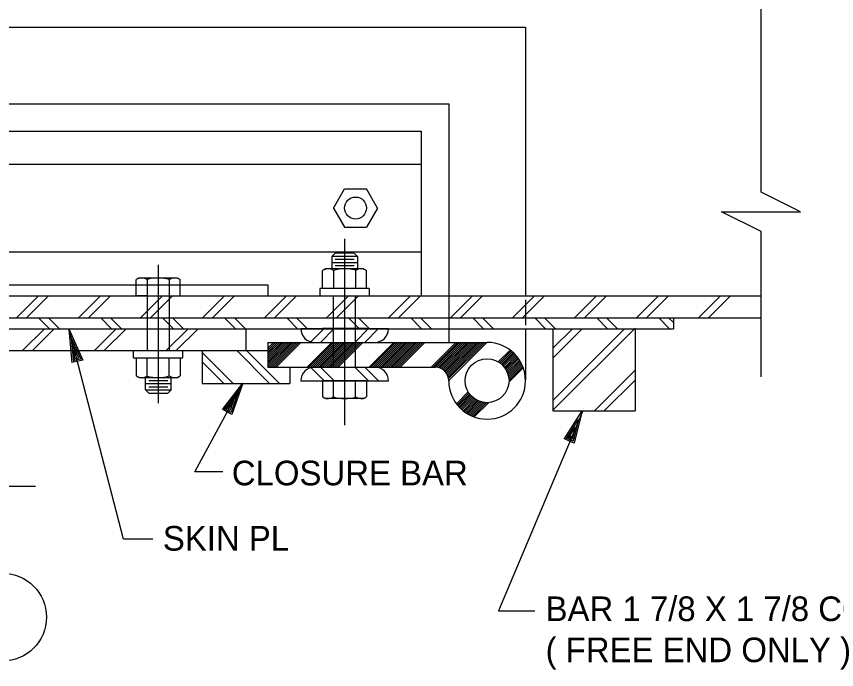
# Model space of a CAD drawing. Extents: x 22371.58 to 22374.41, y 22370.57 to 22372.4.
# Drawn here: x 22372.3521 to 22372.7418, y 22370.9898 to 22371.3 of the extents above; entities that cross this region are included whole.
import ezdxf

# ---------------------------------------------------------------- set-up
doc = ezdxf.new("R2010")
doc.units = 0
for name, color, linetype in [('S-ANNO-DIMS', 7, 'Continuous'), ('S-ANNO-TEXT', 7, 'Continuous'), ('S-GATE-SEAL', 7, 'Continuous'), ('S-SECT-MISC', 7, 'Continuous'), ('S-SECT-SHPS', 7, 'Continuous')]:
    doc.layers.add(name, color=color, linetype=linetype)

msp = doc.modelspace()

# ---------------------------------------------------------------- linework, layer by layer
at = {"layer": 'S-ANNO-DIMS'}
for p, q in [((22372.70594815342, 22371.216615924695), (22372.70594815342, 22371.370740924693)), ((22372.70594815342, 22371.128928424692), (22372.70594815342, 22371.197928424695)), ((22372.37718773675, 22371.151303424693), (22372.37718773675, 22371.151303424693)), ((22372.378271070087, 22371.14710550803), (22372.378271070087, 22371.14710550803)), ((22372.45963565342, 22371.12584509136), (22372.45963565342, 22371.12584509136)), ((22372.45757315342, 22371.12203259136), (22372.45757315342, 22371.12203259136)), ((22372.621312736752, 22371.112678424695), (22372.581165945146, 22371.017772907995)), ((22372.581165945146, 22371.017772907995), (22372.59840552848, 22371.017772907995))]:
    msp.add_line(p, q, dxfattribs=at)
for points in [[(22372.70594815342, 22371.197928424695), (22372.68719815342, 22371.207240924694), (22372.724656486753, 22371.207240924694), (22372.70594815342, 22371.216615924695)], [(22372.41688565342, 22371.051824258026), (22372.402968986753, 22371.051824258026), (22372.37718773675, 22371.151303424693)], [(22372.378593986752, 22371.135574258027), (22372.37718773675, 22371.151303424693), (22372.383593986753, 22371.136865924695), (22372.37932315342, 22371.13576175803), (22372.378271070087, 22371.14710550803), (22372.38262523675, 22371.137303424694), (22372.37988565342, 22371.13659509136), (22372.37932315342, 22371.143074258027), (22372.381646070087, 22371.137740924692), (22372.380521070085, 22371.13744925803), (22372.38040648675, 22371.13887634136)], [(22372.45013565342, 22371.083740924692), (22372.436906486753, 22371.083740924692), (22372.45963565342, 22371.12584509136)], [(22372.449958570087, 22371.113355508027), (22372.45963565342, 22371.12584509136), (22372.45451065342, 22371.11090759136), (22372.450614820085, 22371.11300134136), (22372.45757315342, 22371.12203259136), (22372.45409398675, 22371.111886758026), (22372.451593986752, 22371.11323050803), (22372.455593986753, 22371.118365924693), (22372.453677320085, 22371.112865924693), (22372.452646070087, 22371.113428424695), (22372.45354190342, 22371.114553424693)], [(22372.61241690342, 22371.099334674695), (22372.620864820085, 22371.112678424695), (22372.617177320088, 22371.09731384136), (22372.61310440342, 22371.099043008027), (22372.619177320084, 22371.10868884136), (22372.61666690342, 22371.098251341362), (22372.614052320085, 22371.099355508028), (22372.617552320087, 22371.104845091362), (22372.616156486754, 22371.099199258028), (22372.615083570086, 22371.099647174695), (22372.615864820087, 22371.100855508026)]]:
    msp.add_lwpolyline(points, dxfattribs=at)
at = {"layer": 'S-ANNO-TEXT'}
msp.add_line((22372.153187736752, 22371.076886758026), (22372.36113565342, 22371.076886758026), dxfattribs=at)
msp.add_circle((22372.34553409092, 22371.014738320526), 0.020833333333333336, dxfattribs=at)
at = {"layer": 'S-GATE-SEAL'}
for p, q in [((22371.810114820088, 22371.29497009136), (22372.593968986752, 22371.29497009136)), ((22372.593968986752, 22371.29497009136), (22372.593968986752, 22371.167365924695)), ((22371.810114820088, 22371.258511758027), (22372.55751065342, 22371.258511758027)), ((22372.55751065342, 22371.258511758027), (22372.55751065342, 22371.145230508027)), ((22371.810114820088, 22371.245490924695), (22372.544489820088, 22371.245490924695)), ((22372.544489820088, 22371.245490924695), (22372.544489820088, 22371.167365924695)), ((22371.810114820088, 22371.229865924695), (22372.544489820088, 22371.229865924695)), ((22371.810114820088, 22371.188199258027), (22372.544489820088, 22371.188199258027)), ((22371.810114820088, 22371.172574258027), (22372.47157315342, 22371.172574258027)), ((22372.47157315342, 22371.172574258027), (22372.47157315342, 22371.167365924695)), ((22371.810114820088, 22371.167365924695), (22372.70594815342, 22371.167365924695)), ((22372.593968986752, 22371.165459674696), (22372.593968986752, 22371.153386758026)), ((22371.810114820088, 22371.156949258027), (22372.70594815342, 22371.156949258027)), ((22372.664281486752, 22371.156949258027), (22372.664281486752, 22371.151740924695)), ((22371.810114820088, 22371.151740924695), (22372.664281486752, 22371.151740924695)), ((22372.461156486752, 22371.151740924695), (22372.461156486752, 22371.141324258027)), ((22372.48719815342, 22371.15175134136), (22372.528864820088, 22371.15175134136)), ((22372.593968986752, 22371.151740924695), (22372.593968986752, 22371.127428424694)), ((22372.606989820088, 22371.151740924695), (22372.606989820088, 22371.112678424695)), ((22372.646052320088, 22371.151740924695), (22372.646052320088, 22371.112678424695)), ((22372.47157315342, 22371.145230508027), (22372.47157315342, 22371.133511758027)), ((22372.47157315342, 22371.145230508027), (22372.575739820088, 22371.145230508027)), ((22372.493708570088, 22371.145240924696), (22372.52235440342, 22371.145240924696)), ((22371.810114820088, 22371.141324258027), (22372.47157315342, 22371.141324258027)), ((22372.44032315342, 22371.141324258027), (22372.44032315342, 22371.125699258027)), ((22372.47157315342, 22371.133511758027), (22372.551000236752, 22371.133511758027)), ((22372.481989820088, 22371.133511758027), (22372.481989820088, 22371.125699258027)), ((22372.493708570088, 22371.133511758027), (22372.52235440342, 22371.133511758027)), ((22372.44032315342, 22371.125699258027), (22372.481989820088, 22371.125699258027)), ((22372.48719815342, 22371.12700134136), (22372.528864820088, 22371.12700134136)), ((22372.606989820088, 22371.112678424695), (22372.646052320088, 22371.112678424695))]:
    msp.add_line(p, q, dxfattribs=at)
msp.add_circle((22372.575750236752, 22371.12699613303), 0.010416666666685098, dxfattribs=at)
for centre, radius, start, end in [((22372.493708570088, 22371.151753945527), 0.006510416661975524, 180, 269.9999972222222), ((22372.52235440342, 22371.151753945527), 0.006510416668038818, 270.0000027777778, 0), ((22372.575750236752, 22371.12699613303), 0.01822916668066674, 179.99999999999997, 89.99999722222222), ((22372.493708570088, 22371.126998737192), 0.006510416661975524, 90.00000277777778, 180), ((22372.52235440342, 22371.126998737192), 0.006510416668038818, 0, 89.99999722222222), ((22372.55101065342, 22371.12699613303), 0.006510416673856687, 0, 89.99999722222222)]:
    msp.add_arc(centre, radius, start, end, dxfattribs=at)
at = {"layer": 'S-SECT-MISC'}
for p, q in [((22372.502771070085, 22371.20903259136), (22372.508021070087, 22371.218126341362)), ((22372.508021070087, 22371.218126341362), (22372.518468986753, 22371.218126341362)), ((22372.52371898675, 22371.20903259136), (22372.518468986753, 22371.218126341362)), ((22372.502771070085, 22371.20903259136), (22372.508021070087, 22371.19993884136)), ((22372.52371898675, 22371.20903259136), (22372.518468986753, 22371.19993884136)), ((22372.508021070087, 22371.19993884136), (22372.518468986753, 22371.19993884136)), ((22372.508031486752, 22371.194365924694), (22372.508031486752, 22371.105845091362)), ((22372.50196898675, 22371.18606384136), (22372.503479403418, 22371.187574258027)), ((22372.50196898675, 22371.18606384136), (22372.50196898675, 22371.180199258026)), ((22372.514093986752, 22371.18606384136), (22372.50196898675, 22371.18606384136)), ((22372.51257315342, 22371.187574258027), (22372.503479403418, 22371.187574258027)), ((22372.512562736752, 22371.18454300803), (22372.503541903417, 22371.18454300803)), ((22372.514093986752, 22371.18606384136), (22372.51257315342, 22371.187574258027)), ((22372.514093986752, 22371.18606384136), (22372.514093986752, 22371.180199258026)), ((22372.419489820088, 22371.182074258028), (22372.419489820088, 22371.11631384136)), ((22372.498968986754, 22371.180199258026), (22372.497562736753, 22371.179386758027)), ((22372.517093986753, 22371.180199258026), (22372.498968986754, 22371.180199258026)), ((22372.514093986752, 22371.18303259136), (22372.50196898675, 22371.18303259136)), ((22372.512562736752, 22371.181522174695), (22372.503541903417, 22371.181522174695)), ((22372.517093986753, 22371.180199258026), (22372.518500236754, 22371.179386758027)), ((22372.497562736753, 22371.17075134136), (22372.497562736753, 22371.179386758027)), ((22372.50279190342, 22371.17940759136), (22372.50279190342, 22371.17075134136)), ((22372.513271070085, 22371.17940759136), (22372.513271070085, 22371.17075134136)), ((22372.518500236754, 22371.17075134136), (22372.518500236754, 22371.179386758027)), ((22372.410427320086, 22371.175845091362), (22372.409021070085, 22371.17503259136)), ((22372.409021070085, 22371.167365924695), (22372.409021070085, 22371.17503259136)), ((22372.410427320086, 22371.175845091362), (22372.428552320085, 22371.175845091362)), ((22372.414250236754, 22371.175053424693), (22372.414250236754, 22371.167365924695)), ((22372.424739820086, 22371.175053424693), (22372.424739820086, 22371.167365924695)), ((22372.428552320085, 22371.175845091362), (22372.429958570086, 22371.17503259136)), ((22372.429958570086, 22371.167365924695), (22372.429958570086, 22371.17503259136)), ((22372.496312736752, 22371.17075134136), (22372.496312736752, 22371.167365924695)), ((22372.519750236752, 22371.17075134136), (22372.496312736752, 22371.17075134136)), ((22372.519750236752, 22371.17075134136), (22372.519750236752, 22371.167365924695)), ((22372.409021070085, 22371.167365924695), (22372.429958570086, 22371.167365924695)), ((22372.414323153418, 22371.167365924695), (22372.409021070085, 22371.167365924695)), ((22372.414281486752, 22371.167365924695), (22372.414281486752, 22371.141324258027)), ((22372.42469815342, 22371.167365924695), (22372.42469815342, 22371.141324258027)), ((22372.50282315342, 22371.133511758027), (22372.50282315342, 22371.167365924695)), ((22372.513239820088, 22371.133511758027), (22372.513239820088, 22371.167365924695)), ((22372.42331273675, 22371.141324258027), (22372.43372940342, 22371.151740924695)), ((22372.428031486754, 22371.141324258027), (22372.438448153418, 22371.151740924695)), ((22372.518500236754, 22371.15175134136), (22372.497562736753, 22371.15175134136)), ((22372.513198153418, 22371.15175134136), (22372.518500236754, 22371.15175134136)), ((22372.407771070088, 22371.137928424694), (22372.407771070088, 22371.141324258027)), ((22372.431208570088, 22371.137928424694), (22372.431208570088, 22371.141324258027)), ((22372.407771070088, 22371.137928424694), (22372.431208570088, 22371.137928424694)), ((22372.409031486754, 22371.137928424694), (22372.409031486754, 22371.129293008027)), ((22372.414250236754, 22371.129272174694), (22372.414250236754, 22371.137928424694)), ((22372.424739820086, 22371.129272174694), (22372.424739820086, 22371.137928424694)), ((22372.429958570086, 22371.137928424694), (22372.429958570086, 22371.129293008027)), ((22372.410427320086, 22371.12848050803), (22372.409031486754, 22371.129293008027)), ((22372.410427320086, 22371.12848050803), (22372.428562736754, 22371.12848050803)), ((22372.41343773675, 22371.12262634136), (22372.41343773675, 22371.12848050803)), ((22372.41343773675, 22371.12565759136), (22372.425562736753, 22371.12565759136)), ((22372.41496898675, 22371.127168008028), (22372.42397940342, 22371.127168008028)), ((22372.425562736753, 22371.12262634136), (22372.425562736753, 22371.12848050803)), ((22372.428562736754, 22371.12848050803), (22372.429958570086, 22371.129293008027)), ((22372.518500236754, 22371.12700134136), (22372.497562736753, 22371.12700134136)), ((22372.497562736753, 22371.12700134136), (22372.497562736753, 22371.119324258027)), ((22372.502781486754, 22371.119303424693), (22372.502781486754, 22371.12700134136)), ((22372.513271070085, 22371.119303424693), (22372.513271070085, 22371.12700134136)), ((22372.518500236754, 22371.12700134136), (22372.518500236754, 22371.119324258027)), ((22372.41343773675, 22371.12262634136), (22372.425562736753, 22371.12262634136)), ((22372.41343773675, 22371.12262634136), (22372.41494815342, 22371.121105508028)), ((22372.41496898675, 22371.124136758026), (22372.42397940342, 22371.124136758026)), ((22372.425562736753, 22371.12262634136), (22372.424041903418, 22371.121105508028)), ((22372.41494815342, 22371.121105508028), (22372.424041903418, 22371.121105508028)), ((22372.498968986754, 22371.118511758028), (22372.497562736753, 22371.119324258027)), ((22372.517093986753, 22371.118511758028), (22372.498968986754, 22371.118511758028)), ((22372.517093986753, 22371.118511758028), (22372.518500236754, 22371.119324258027))]:
    msp.add_line(p, q, dxfattribs=at)
for points in [[(22372.411083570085, 22371.156949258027), (22372.421500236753, 22371.167365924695)], [(22372.41579190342, 22371.156949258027), (22372.42621898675, 22371.167365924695)], [(22372.499468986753, 22371.15693884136), (22372.50988565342, 22371.167365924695)], [(22372.50418773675, 22371.156949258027), (22372.51460440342, 22371.167365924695)], [(22372.42679190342, 22371.151740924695), (22372.421583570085, 22371.156949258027)], [(22372.43151065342, 22371.151730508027), (22372.426302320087, 22371.156949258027)], [(22372.515187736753, 22371.151730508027), (22372.509968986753, 22371.156949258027)], [(22372.519896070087, 22371.151730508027), (22372.51468773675, 22371.156949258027)], [(22372.498333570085, 22371.15175134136), (22372.49204190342, 22371.145459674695)], [(22372.50304190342, 22371.15175134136), (22372.49654190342, 22371.145240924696)], [(22372.519468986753, 22371.15175134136), (22372.512958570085, 22371.145240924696)]]:
    msp.add_lwpolyline(points, dxfattribs=at)
msp.add_circle((22372.513245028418, 22371.209029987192), 0.005208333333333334, dxfattribs=at)
for centre, radius, start, end in [((22372.500211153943, 22371.175664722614), 0.004545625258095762, 55.489019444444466, 120.28758611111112), ((22372.508097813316, 22371.16202027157), 0.018182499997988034, 73.50340833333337, 106.98162777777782), ((22372.515848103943, 22371.175664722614), 0.004545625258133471, 59.71241111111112, 124.5109777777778), ((22372.41167664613, 22371.171309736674), 0.004545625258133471, 55.489019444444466, 120.28758611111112), ((22372.419426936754, 22371.157665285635), 0.018182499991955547, 73.01836944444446, 106.49658888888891), ((22372.427313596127, 22371.171309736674), 0.004545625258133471, 59.71241111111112, 124.5109777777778), ((22372.411678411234, 22371.13302025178), 0.004545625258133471, 239.71241111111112, 304.5109777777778), ((22372.419428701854, 22371.14666470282), 0.018182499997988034, 253.50340833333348, 286.98162777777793), ((22372.427315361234, 22371.13302025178), 0.004545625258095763, 235.48901944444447, 300.2875861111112), ((22372.500212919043, 22371.12305232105), 0.004545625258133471, 239.71241111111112, 304.5109777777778), ((22372.50809957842, 22371.136696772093), 0.018182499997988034, 253.01837222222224, 286.4965916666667), ((22372.515849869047, 22371.12305232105), 0.004545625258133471, 235.48901944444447, 300.2875861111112)]:
    msp.add_arc(centre, radius, start, end, dxfattribs=at)
at = {"layer": 'S-SECT-SHPS'}
for p, q in [((22372.354958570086, 22371.141324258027), (22372.365375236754, 22371.151740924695)), ((22372.358771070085, 22371.151740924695), (22372.358771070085, 22371.151740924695)), ((22372.359677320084, 22371.141324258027), (22372.370093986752, 22371.151740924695)), ((22372.38913565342, 22371.141324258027), (22372.399552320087, 22371.151740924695)), ((22372.39385440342, 22371.141324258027), (22372.404271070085, 22371.151740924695)), ((22372.36126065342, 22371.148188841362), (22372.36126065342, 22371.148188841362)), ((22372.48166690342, 22371.145230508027), (22372.47157315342, 22371.13513675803)), ((22372.47982315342, 22371.145230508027), (22372.47157315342, 22371.13698050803)), ((22372.47797940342, 22371.145230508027), (22372.47157315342, 22371.13882425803)), ((22372.476146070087, 22371.145230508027), (22372.47157315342, 22371.14065759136)), ((22372.474302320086, 22371.145230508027), (22372.47157315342, 22371.14250134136)), ((22372.475218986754, 22371.145230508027), (22372.47157315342, 22371.141584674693)), ((22372.477062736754, 22371.145230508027), (22372.47157315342, 22371.139740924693)), ((22372.47890648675, 22371.145230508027), (22372.47157315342, 22371.137897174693)), ((22372.48075023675, 22371.145230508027), (22372.47157315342, 22371.136053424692)), ((22372.482583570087, 22371.145230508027), (22372.47157315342, 22371.13422009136)), ((22372.48351065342, 22371.145230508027), (22372.47179190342, 22371.133511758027)), ((22372.484427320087, 22371.145230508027), (22372.472708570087, 22371.133511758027)), ((22372.48534398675, 22371.145230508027), (22372.47362523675, 22371.133511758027)), ((22372.486271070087, 22371.145230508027), (22372.474552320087, 22371.133511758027)), ((22372.48718773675, 22371.145230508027), (22372.47546898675, 22371.133511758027)), ((22372.50191690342, 22371.145230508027), (22372.49019815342, 22371.133511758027)), ((22372.502833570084, 22371.145230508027), (22372.491114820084, 22371.133511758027)), ((22372.50376065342, 22371.145230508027), (22372.49204190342, 22371.133511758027)), ((22372.504677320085, 22371.145230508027), (22372.492958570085, 22371.133511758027)), ((22372.50560440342, 22371.145230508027), (22372.49388565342, 22371.133511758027)), ((22372.506521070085, 22371.145230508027), (22372.494802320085, 22371.133511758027)), ((22372.507437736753, 22371.145230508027), (22372.495718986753, 22371.133511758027)), ((22372.508364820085, 22371.145230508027), (22372.496646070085, 22371.133511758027)), ((22372.509281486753, 22371.145230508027), (22372.497562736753, 22371.133511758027)), ((22372.51019815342, 22371.145230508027), (22372.49847940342, 22371.133511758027)), ((22372.511125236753, 22371.145230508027), (22372.499406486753, 22371.133511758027)), ((22372.512041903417, 22371.145230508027), (22372.500323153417, 22371.133511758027)), ((22372.512968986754, 22371.145230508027), (22372.501250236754, 22371.133511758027)), ((22372.513885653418, 22371.145230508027), (22372.502166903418, 22371.133511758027)), ((22372.514802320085, 22371.145230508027), (22372.503083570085, 22371.133511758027)), ((22372.515729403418, 22371.145230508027), (22372.504010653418, 22371.133511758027)), ((22372.516646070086, 22371.145230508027), (22372.504927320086, 22371.133511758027)), ((22372.53138565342, 22371.145230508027), (22372.51966690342, 22371.133511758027)), ((22372.532302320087, 22371.145230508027), (22372.520583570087, 22371.133511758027)), ((22372.53321898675, 22371.145230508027), (22372.52150023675, 22371.133511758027)), ((22372.534146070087, 22371.145230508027), (22372.522427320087, 22371.133511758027)), ((22372.53506273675, 22371.145230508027), (22372.52334398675, 22371.133511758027)), ((22372.53597940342, 22371.145230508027), (22372.52426065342, 22371.133511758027)), ((22372.536906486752, 22371.145230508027), (22372.525187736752, 22371.133511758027)), ((22372.53782315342, 22371.145230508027), (22372.52610440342, 22371.133511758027)), ((22372.538750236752, 22371.145230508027), (22372.527031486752, 22371.133511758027)), ((22372.53966690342, 22371.145230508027), (22372.52794815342, 22371.133511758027)), ((22372.540583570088, 22371.145230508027), (22372.528864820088, 22371.133511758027)), ((22372.54151065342, 22371.145230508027), (22372.52979190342, 22371.133511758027)), ((22372.542427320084, 22371.145230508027), (22372.530708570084, 22371.133511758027)), ((22372.543343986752, 22371.145230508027), (22372.531625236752, 22371.133511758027)), ((22372.544271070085, 22371.145230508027), (22372.532552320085, 22371.133511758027)), ((22372.545187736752, 22371.145230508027), (22372.533468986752, 22371.133511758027)), ((22372.546114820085, 22371.145230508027), (22372.534396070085, 22371.133511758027)), ((22372.560843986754, 22371.145230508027), (22372.549125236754, 22371.133511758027)), ((22372.561771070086, 22371.145230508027), (22372.550052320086, 22371.133511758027)), ((22372.562677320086, 22371.14522009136), (22372.550958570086, 22371.13350134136)), ((22372.563604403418, 22371.145230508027), (22372.551833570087, 22371.133449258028)), ((22372.564521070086, 22371.14522009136), (22372.55260440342, 22371.133303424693)), ((22372.56544815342, 22371.145230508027), (22372.553312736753, 22371.133084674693)), ((22372.566364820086, 22371.14522009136), (22372.553948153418, 22371.132803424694)), ((22372.56729190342, 22371.145230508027), (22372.554531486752, 22371.13247009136)), ((22372.568208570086, 22371.14522009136), (22372.55507315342, 22371.132084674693)), ((22372.56913565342, 22371.145230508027), (22372.555531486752, 22371.13162634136)), ((22372.57004190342, 22371.14522009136), (22372.556000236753, 22371.131178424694)), ((22372.57096898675, 22371.145230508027), (22372.556458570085, 22371.13072009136)), ((22372.57188565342, 22371.14522009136), (22372.556739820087, 22371.130074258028)), ((22372.57281273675, 22371.145230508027), (22372.55704190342, 22371.129449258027)), ((22372.57372940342, 22371.14522009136), (22372.557271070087, 22371.128772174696)), ((22372.57465648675, 22371.145230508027), (22372.557437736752, 22371.128011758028)), ((22372.57557315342, 22371.14522009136), (22372.557521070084, 22371.127168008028)), ((22372.47241690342, 22371.125699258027), (22372.45679190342, 22371.141324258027)), ((22372.47707315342, 22371.125699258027), (22372.46144815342, 22371.141324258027)), ((22372.58666690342, 22371.14159509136), (22372.58104190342, 22371.13597009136)), ((22372.587187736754, 22371.14118884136), (22372.581604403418, 22371.13560550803)), ((22372.455021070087, 22371.125699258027), (22372.44032315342, 22371.140397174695)), ((22372.587687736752, 22371.140772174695), (22372.582135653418, 22371.13522009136)), ((22372.588146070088, 22371.140313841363), (22372.582646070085, 22371.134803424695)), ((22372.588646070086, 22371.13988675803), (22372.583114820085, 22371.134355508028)), ((22372.589104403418, 22371.139418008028), (22372.58357315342, 22371.133897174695)), ((22372.589531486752, 22371.138928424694), (22372.58397940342, 22371.13337634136)), ((22372.589948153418, 22371.138428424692), (22372.584437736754, 22371.13291800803)), ((22372.59035440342, 22371.13790759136), (22372.584718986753, 22371.13228259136)), ((22372.590739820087, 22371.13737634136), (22372.585052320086, 22371.13168884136)), ((22372.450614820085, 22371.125699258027), (22372.44032315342, 22371.135990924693)), ((22372.59110440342, 22371.13682425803), (22372.585343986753, 22371.13106384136)), ((22372.59144815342, 22371.136251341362), (22372.585593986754, 22371.130397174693)), ((22372.591781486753, 22371.13565759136), (22372.585812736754, 22371.12968884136)), ((22372.59210440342, 22371.135053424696), (22372.58597940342, 22371.12893884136)), ((22372.592396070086, 22371.134428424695), (22372.58610440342, 22371.128136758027)), ((22372.59266690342, 22371.13378259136), (22372.58616690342, 22371.127282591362)), ((22372.59291690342, 22371.133115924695), (22372.586146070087, 22371.126334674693)), ((22372.513198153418, 22371.12700134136), (22372.518500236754, 22371.12700134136)), ((22372.566781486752, 22371.121699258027), (22372.561156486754, 22371.11607425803)), ((22372.56713565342, 22371.12113675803), (22372.561614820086, 22371.115615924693)), ((22372.567521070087, 22371.120605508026), (22372.561968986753, 22371.115053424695)), ((22372.567937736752, 22371.120105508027), (22372.562437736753, 22371.11459509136)), ((22372.56838565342, 22371.119626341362), (22372.562864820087, 22371.114105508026)), ((22372.56884398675, 22371.119168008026), (22372.56332315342, 22371.113636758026)), ((22372.569364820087, 22371.11876175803), (22372.563812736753, 22371.11322009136)), ((22372.569896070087, 22371.11837634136), (22372.56431273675, 22371.112793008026)), ((22372.570458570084, 22371.118022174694), (22372.564833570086, 22371.112397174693)), ((22372.57106273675, 22371.117699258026), (22372.565375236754, 22371.11201175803)), ((22372.571687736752, 22371.117407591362), (22372.56591690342, 22371.11163675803)), ((22372.57235440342, 22371.117147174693), (22372.566489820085, 22371.111293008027)), ((22372.573052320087, 22371.116928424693), (22372.567083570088, 22371.110959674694)), ((22372.573802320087, 22371.11676175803), (22372.56768773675, 22371.110647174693)), ((22372.57460440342, 22371.116636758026), (22372.568312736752, 22371.110355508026)), ((22372.575468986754, 22371.116584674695), (22372.568958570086, 22371.110074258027)), ((22372.57640648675, 22371.11659509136), (22372.569625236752, 22371.109824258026)), ((22372.621416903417, 22371.113980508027), (22372.621416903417, 22371.113980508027)), ((22372.61972940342, 22371.109990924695), (22372.61972940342, 22371.109990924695))]:
    msp.add_line(p, q, dxfattribs=at)
for points in [[(22372.35215648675, 22371.156949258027), (22372.36257315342, 22371.167365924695)], [(22372.356875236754, 22371.156949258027), (22372.367291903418, 22371.167365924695)], [(22372.381614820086, 22371.156949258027), (22372.39204190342, 22371.167365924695)], [(22372.386333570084, 22371.156949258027), (22372.396750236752, 22371.167365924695)], [(22372.44054190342, 22371.156949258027), (22372.450958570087, 22371.167365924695)], [(22372.445260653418, 22371.156949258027), (22372.455677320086, 22371.167365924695)], [(22372.47001065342, 22371.156949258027), (22372.480427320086, 22371.167365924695)], [(22372.474718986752, 22371.156949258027), (22372.48513565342, 22371.167365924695)], [(22372.52893773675, 22371.156949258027), (22372.53935440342, 22371.167365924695)], [(22372.533646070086, 22371.156949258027), (22372.544062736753, 22371.167365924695)], [(22372.558396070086, 22371.156949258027), (22372.568812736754, 22371.167365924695)], [(22372.563114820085, 22371.156949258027), (22372.573531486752, 22371.167365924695)], [(22372.58785440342, 22371.156949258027), (22372.598271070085, 22371.167365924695)], [(22372.59257315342, 22371.156949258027), (22372.602989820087, 22371.167365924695)], [(22372.61732315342, 22371.156949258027), (22372.627739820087, 22371.167365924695)], [(22372.622031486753, 22371.156949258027), (22372.632448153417, 22371.167365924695)], [(22372.646781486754, 22371.15693884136), (22372.657198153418, 22371.167365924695)], [(22372.651500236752, 22371.15693884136), (22372.66191690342, 22371.167365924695)], [(22372.676250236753, 22371.156949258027), (22372.68666690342, 22371.167365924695)], [(22372.680958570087, 22371.156949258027), (22372.69137523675, 22371.167365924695)], [(22372.367875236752, 22371.151730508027), (22372.36265648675, 22371.156949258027)], [(22372.372583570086, 22371.151740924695), (22372.367375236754, 22371.156949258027)], [(22372.397333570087, 22371.151730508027), (22372.39212523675, 22371.156949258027)], [(22372.402052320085, 22371.151730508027), (22372.396833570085, 22371.156949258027)], [(22372.45626065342, 22371.151740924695), (22372.45104190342, 22371.156949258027)], [(22372.460968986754, 22371.151740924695), (22372.455760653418, 22371.156949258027)], [(22372.48571898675, 22371.151730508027), (22372.48051065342, 22371.156949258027)], [(22372.490437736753, 22371.151740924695), (22372.48522940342, 22371.156949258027)], [(22372.544646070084, 22371.151740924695), (22372.539437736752, 22371.156949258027)], [(22372.549364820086, 22371.151730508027), (22372.544146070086, 22371.156949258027)], [(22372.57410440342, 22371.151740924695), (22372.568896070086, 22371.156949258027)], [(22372.57882315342, 22371.151740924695), (22372.573614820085, 22371.156949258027)], [(22372.603573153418, 22371.151730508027), (22372.598364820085, 22371.156949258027)], [(22372.60828148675, 22371.151740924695), (22372.60307315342, 22371.156949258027)], [(22372.633031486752, 22371.151730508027), (22372.62782315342, 22371.156949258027)], [(22372.637750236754, 22371.151730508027), (22372.63254190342, 22371.156949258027)], [(22372.66250023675, 22371.151740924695), (22372.65729190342, 22371.156949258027)], [(22372.664281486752, 22371.15466800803), (22372.662000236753, 22371.156949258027)], [(22372.705708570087, 22371.156949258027), (22372.70594815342, 22371.15718884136)], [(22372.524177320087, 22371.15175134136), (22372.517677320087, 22371.145240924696)], [(22372.606989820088, 22371.112980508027), (22372.646052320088, 22371.152043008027)], [(22372.606989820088, 22371.142449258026), (22372.61631273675, 22371.151740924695)], [(22372.606989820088, 22371.117699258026), (22372.641031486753, 22371.151740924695)], [(22372.606989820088, 22371.137730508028), (22372.62100023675, 22371.151740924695)], [(22372.498333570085, 22371.12700134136), (22372.49204190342, 22371.133293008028)], [(22372.50304190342, 22371.12700134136), (22372.49654190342, 22371.133511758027)], [(22372.519468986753, 22371.12700134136), (22372.512958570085, 22371.133511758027)], [(22372.524177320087, 22371.12700134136), (22372.517677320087, 22371.133511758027)], [(22372.626718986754, 22371.112678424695), (22372.646052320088, 22371.13201175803)], [(22372.631427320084, 22371.112678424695), (22372.646052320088, 22371.127303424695)]]:
    msp.add_lwpolyline(points, dxfattribs=at)

# ---------------------------------------------------------------- texts
at = {"layer": 'S-ANNO-DIMS'}
for s, p in [('CLOSURE BAR', (22372.454437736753, 22371.077345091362)), ('BAR 1 7/8 X 1 7/8 CONT', (22372.60355092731, 22371.012872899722)), ('( FREE END ONLY )', (22372.60355092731, 22370.993362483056))]:
    msp.add_text(s, height=0.011697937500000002, dxfattribs=at).set_placement(p)
at = {"layer": 'S-ANNO-TEXT'}
msp.add_text('SKIN PL', height=0.011697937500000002, dxfattribs=at).set_placement((22372.421677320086, 22371.046334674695))

doc.saveas('drawing.dxf')
